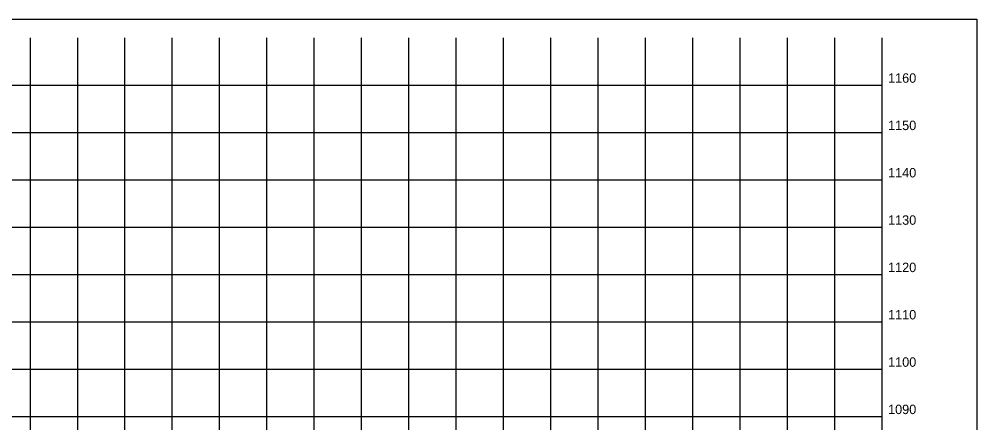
# Model space of a CAD drawing. Extents: x 1131015 to 1136271, y 133453 to 174329.
# Drawn here: x 1131308.1 to 1131510.5, y 155242.3 to 155327.6 of the extents above; entities that cross this region are included whole.
import ezdxf

# ---------------------------------------------------------------- set-up
doc = ezdxf.new("R2010")
doc.units = 0
for name, color, linetype in [('DESIGN - SHEET - Corner Text', 7, 'Continuous'), ('DESIGN - SHEET - Linework', 7, 'Continuous'), ('DESIGN - SHEET - Plot Shape', 7, 'Continuous')]:
    doc.layers.add(name, color=color, linetype=linetype)

msp = doc.modelspace()

# ---------------------------------------------------------------- linework, layer by layer
at = {"layer": 'DESIGN - SHEET - Linework'}
for p, q in [((1131310.46, 155113.66), (1131310.46, 155323.66)), ((1131320.46, 155113.66), (1131320.46, 155323.66)), ((1131330.46, 155113.66), (1131330.46, 155323.66)), ((1131340.46, 155113.66), (1131340.46, 155323.66)), ((1131350.46, 155113.66), (1131350.46, 155323.66)), ((1131360.46, 155113.66), (1131360.46, 155323.66)), ((1131370.46, 155113.66), (1131370.46, 155323.66)), ((1131380.46, 155113.66), (1131380.46, 155323.66)), ((1131390.46, 155113.66), (1131390.46, 155323.66)), ((1131400.46, 155113.66), (1131400.46, 155323.66)), ((1131410.46, 155113.66), (1131410.46, 155323.66)), ((1131420.46, 155113.66), (1131420.46, 155323.66)), ((1131430.46, 155113.66), (1131430.46, 155323.66)), ((1131440.46, 155113.66), (1131440.46, 155323.66)), ((1131450.46, 155113.66), (1131450.46, 155323.66)), ((1131460.46, 155113.66), (1131460.46, 155323.66)), ((1131470.46, 155113.66), (1131470.46, 155323.66)), ((1131480.46, 155113.66), (1131480.46, 155323.66)), ((1131190.46, 155313.66), (1131490.46, 155313.66)), ((1131190.46, 155303.66), (1131490.46, 155303.66)), ((1131190.46, 155293.66), (1131490.46, 155293.66)), ((1131190.46, 155283.66), (1131490.46, 155283.66)), ((1131190.46, 155273.66), (1131490.46, 155273.66)), ((1131190.46, 155263.66), (1131490.46, 155263.66)), ((1131190.46, 155253.66), (1131490.46, 155253.66)), ((1131190.46, 155243.66), (1131490.46, 155243.66))]:
    msp.add_line(p, q, dxfattribs=at)
msp.add_lwpolyline([(1131190.46, 155323.66), (1131190.46, 155113.66), (1131490.46, 155113.66), (1131490.46, 155323.66)], dxfattribs=at)
at = {"layer": 'DESIGN - SHEET - Plot Shape'}
msp.add_lwpolyline([(1131170.46, 155327.6), (1131510.46, 155327.6), (1131510.46, 155109.72), (1131170.46, 155109.72)], close=True, dxfattribs=at)

# ---------------------------------------------------------------- texts
at = {"layer": 'DESIGN - SHEET - Corner Text'}
for s, p in [('1160', (1131491.7, 155314.16)), ('1150', (1131491.7, 155304.16)), ('1140', (1131491.7, 155294.16)), ('1130', (1131491.7, 155284.16)), ('1120', (1131491.7, 155274.16)), ('1110', (1131491.7, 155264.16)), ('1100', (1131491.7, 155254.16)), ('1090', (1131491.7, 155244.16))]:
    msp.add_text(s, height=2, dxfattribs=at).set_placement(p)

doc.saveas('drawing.dxf')
